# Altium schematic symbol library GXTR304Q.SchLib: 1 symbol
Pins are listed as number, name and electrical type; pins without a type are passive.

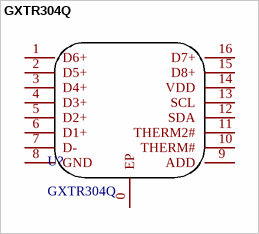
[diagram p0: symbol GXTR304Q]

## GXTR304Q
designator U?
footprint QFN16-EP(3*3) P=0.5
pins: 0 EP, 1 D6+, 2 D5+, 3 D4+, 4 D3+, 5 D2+, 6 D1+, 7 D-, 8 GND, 9 ADD, 10 THERM#, 11 THERM2#, 12 SDA, 13 SCL, 14 VDD, 15 D8+, 16 D7+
